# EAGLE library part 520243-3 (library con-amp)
AMP connector
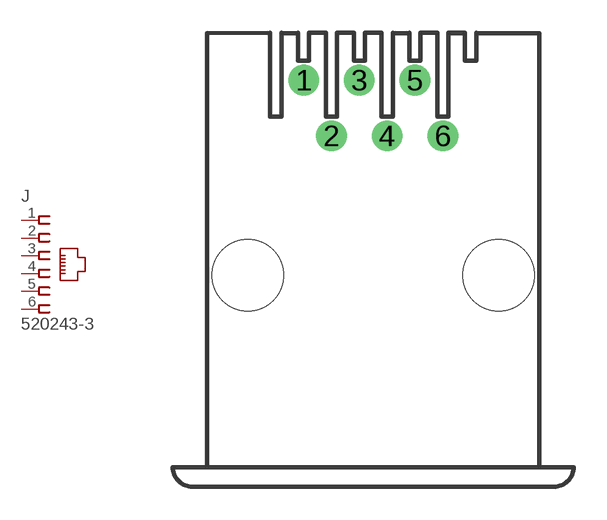
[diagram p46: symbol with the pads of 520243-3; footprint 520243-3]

Designator prefix J

## 520243-3 (OC_FARNELL: unknown; OC_NEWARK: unknown)  [520243-3]
1  1  pas
2  2  pas
3  3  pas
4  4  pas
5  5  pas
6  6  pas

## Footprint 520243-3 (pad centres in mm)
Modular Jack with Flanged
drill 0.889 round: 1 -3.175,8.89; 2 -1.905,6.35; 3 -0.635,8.89; 4 0.635,6.35; 5 1.905,8.89; 6 3.175,6.35
hole 3.251 at -5.715,0
hole 3.251 at 5.715,0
